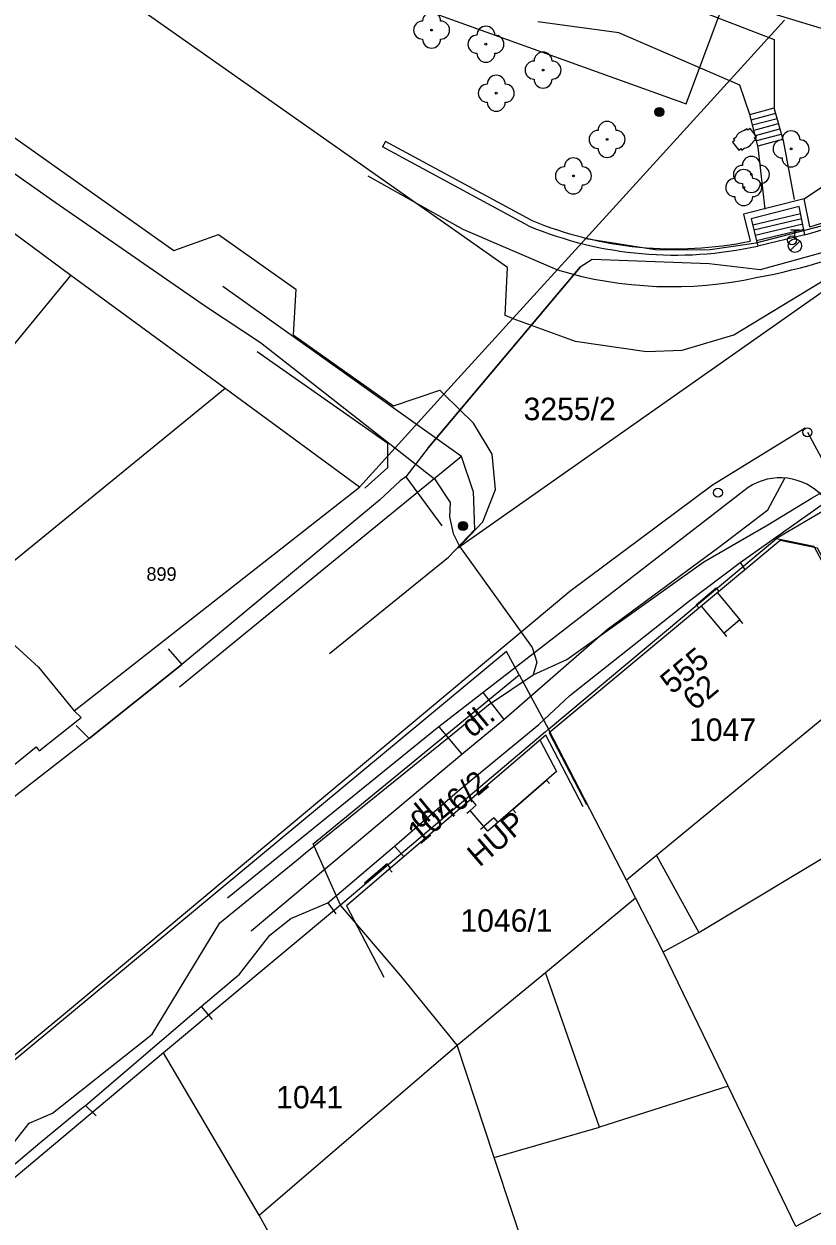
# Model space of a CAD drawing. Extents: x -601580 to 4, y -1204314 to 4.
# Drawn here: x -600094.3 to -600050.6, y -1203405.4 to -1203338.9 of the extents above; entities that cross this region are included whole.
import ezdxf

# ---------------------------------------------------------------- set-up
doc = ezdxf.new("R2010")
doc.units = 0
for name, color, linetype in [('00-KN-HRANICE PARCEL', 7, 'Continuous'), ('00-KN-PARC. CISLA', 7, 'Continuous'), ('00-KN-VNITRNI KRESBA', 7, 'Continuous'), ('00-POLOHOPIS', 7, 'Continuous'), ('00-SITE KOM. KABEL', 7, 'Continuous'), ('00-VAK-KANAL-POTRUBI', 7, 'Continuous'), ('00-VAK-VODA-RAD IGIS', 7, 'Continuous'), ('Vrstva 22', 7, 'Continuous'), ('Vrstva 25', 7, 'Continuous'), ('Vrstva 28', 7, 'Continuous'), ('Vrstva 6', 7, 'Continuous')]:
    doc.layers.add(name, color=color, linetype=linetype)

# ---------------------------------------------------------------- blocks, each defined once
blk = doc.blocks.new('6.01A_18')
at = {"layer": 'Vrstva 25'}
for radius in [0.25, 0.2, 0.15, 0.1, 0.05]:
    blk.add_circle((0, 0), radius, dxfattribs=at)
blk = doc.blocks.new('6.01A_1416')
at = {"layer": 'Vrstva 25'}
for radius in [0.25, 0.2, 0.15, 0.1, 0.05]:
    blk.add_circle((0, 0), radius, dxfattribs=at)
blk = doc.blocks.new('6.14A_536')
at = {"layer": 'Vrstva 28'}
blk.add_circle((0, 0), 0.25, dxfattribs=at)
blk = doc.blocks.new('6.14A_546')
at = {"layer": 'Vrstva 28'}
blk.add_circle((0, 0), 0.25, dxfattribs=at)
blk = doc.blocks.new('6.13_126')
at = {"layer": 'Vrstva 28'}
for p, q in [((-0.25, 0.875), (0.25, 0.875)), ((0, 0.375), (0, 0.875)), ((-0.258, -0.272), (0.272, 0.258))]:
    blk.add_line(p, q, dxfattribs=at)
blk.add_circle((0, 0), 0.375, dxfattribs=at)
blk = doc.blocks.new('6.14A_608')
at = {"layer": 'Vrstva 28'}
blk.add_circle((0, 0), 0.25, dxfattribs=at)
blk = doc.blocks.new('3.13_764')
at = {"layer": 'Vrstva 22'}
blk.add_circle((0, 0), 0.05, dxfattribs=at)
for centre, start, end in [((0, 0.5), 0, 180), ((-0.5, 0), 90, 270), ((0.5, 0), 270, 90), ((0, -0.5), 180, 0)]:
    blk.add_arc(centre, 0.5, start, end, dxfattribs=at)
blk = doc.blocks.new('3.13_766')
at = {"layer": 'Vrstva 22'}
blk.add_circle((0, 0), 0.05, dxfattribs=at)
for centre, start, end in [((0, 0.5), 0, 180), ((-0.5, 0), 90, 270), ((0.5, 0), 270, 90), ((0, -0.5), 180, 0)]:
    blk.add_arc(centre, 0.5, start, end, dxfattribs=at)
blk = doc.blocks.new('3.13_768')
at = {"layer": 'Vrstva 22'}
blk.add_circle((0, 0), 0.05, dxfattribs=at)
for centre, start, end in [((0, 0.5), 0, 180), ((-0.5, 0), 90, 270), ((0.5, 0), 270, 90), ((0, -0.5), 180, 0)]:
    blk.add_arc(centre, 0.5, start, end, dxfattribs=at)
blk = doc.blocks.new('3.13_770')
at = {"layer": 'Vrstva 22'}
blk.add_circle((0, 0), 0.05, dxfattribs=at)
for centre, start, end in [((0, 0.5), 0, 180), ((-0.5, 0), 90, 270), ((0.5, 0), 270, 90), ((0, -0.5), 180, 0)]:
    blk.add_arc(centre, 0.5, start, end, dxfattribs=at)
blk = doc.blocks.new('3.13_772')
at = {"layer": 'Vrstva 22'}
blk.add_circle((0, 0), 0.05, dxfattribs=at)
for centre, start, end in [((0, 0.5), 0, 180), ((-0.5, 0), 90, 270), ((0.5, 0), 270, 90), ((0, -0.5), 180, 0)]:
    blk.add_arc(centre, 0.5, start, end, dxfattribs=at)
blk = doc.blocks.new('3.13_774')
at = {"layer": 'Vrstva 22'}
blk.add_circle((0, 0), 0.05, dxfattribs=at)
for centre, start, end in [((0, 0.5), 0, 180), ((-0.5, 0), 90, 270), ((0.5, 0), 270, 90), ((0, -0.5), 180, 0)]:
    blk.add_arc(centre, 0.5, start, end, dxfattribs=at)
blk = doc.blocks.new('VCHOD_1184')
at = {"layer": 'Vrstva 6'}
blk.add_line((0, 0.25), (0, 0), dxfattribs=at)
blk = doc.blocks.new('VCHOD_1186')
at = {"layer": 'Vrstva 6'}
blk.add_line((0, 0.25), (0, 0), dxfattribs=at)
blk = doc.blocks.new('VCHOD_1190')
at = {"layer": 'Vrstva 6'}
blk.add_line((0, 0.25), (0, 0), dxfattribs=at)
blk = doc.blocks.new('VCHOD_1192')
at = {"layer": 'Vrstva 6'}
blk.add_line((0, 0.25), (0, 0), dxfattribs=at)
blk = doc.blocks.new('VCHOD_1194')
at = {"layer": 'Vrstva 6'}
blk.add_line((0, 0.25), (0, 0), dxfattribs=at)
blk = doc.blocks.new('VCHOD_1196')
at = {"layer": 'Vrstva 6'}
blk.add_line((0, 0.25), (0, 0), dxfattribs=at)
blk = doc.blocks.new('VCHOD_1198')
at = {"layer": 'Vrstva 6'}
blk.add_line((0, 0.25), (0, 0), dxfattribs=at)
blk = doc.blocks.new('3.13B')
at = {"layer": 'Vrstva 22'}
blk.add_circle((0, 0), 0.05, dxfattribs=at)
for centre, start, end in [((0, 0.5), 0, 180), ((-0.5, 0), 90, 270), ((0.5, 0), 270, 90), ((0, -0.5), 180, 0)]:
    blk.add_arc(centre, 0.5, start, end, dxfattribs=at)
blk = doc.blocks.new('3.13B_2')
at = {"layer": 'Vrstva 22'}
blk.add_circle((0, 0), 0.05, dxfattribs=at)
for centre, start, end in [((0, 0.5), 0, 180), ((-0.5, 0), 90, 270), ((0.5, 0), 270, 90), ((0, -0.5), 180, 0)]:
    blk.add_arc(centre, 0.5, start, end, dxfattribs=at)
blk = doc.blocks.new('3.13B_4')
at = {"layer": 'Vrstva 22'}
blk.add_circle((0, 0), 0.05, dxfattribs=at)
for centre, start, end in [((0, 0.5), 0, 180), ((-0.5, 0), 90, 270), ((0.5, 0), 270, 90), ((0, -0.5), 180, 0)]:
    blk.add_arc(centre, 0.5, start, end, dxfattribs=at)

msp = doc.modelspace()

# ---------------------------------------------------------------- linework, layer by layer
at = {"layer": '00-KN-HRANICE PARCEL'}
for p, q in [((-600052.12, -1203338.71), (-600063.14, -1203350.82)), ((-600063.14, -1203350.82), (-600067.18, -1203355.26)), ((-600071.01, -1203359.47), (-600067.18, -1203355.26)), ((-600071.01, -1203359.47), (-600075.7, -1203364.62)), ((-600042.39, -1203361.48), (-600052.56, -1203367.47)), ((-600091.52, -1203377.04), (-600075.7, -1203364.62)), ((-600065.2, -1203378.06), (-600052.56, -1203367.47)), ((-600066.83, -1203375.04), (-600065.2, -1203378.06)), ((-600076.74, -1203387.83), (-600086.56, -1203396.02)), ((-600086.56, -1203396.02), (-600096.33, -1203404.2))]:
    msp.add_line(p, q, dxfattribs=at)
for points in [[(-600140, -1203318.23), (-600138.91, -1203317.26), (-600137.57, -1203316.43), (-600136.11, -1203315.95), (-600133.54, -1203315.93), (-600130.69, -1203317.16), (-600130.97, -1203319.63), (-600120.34, -1203327.24), (-600117.91, -1203326.29), (-600112.74, -1203329.92), (-600113.21, -1203332.34), (-600107.76, -1203336.15), (-600105.34, -1203335.13), (-600101.46, -1203337.9), (-600101.76, -1203340.34), (-600086, -1203351.5), (-600083.51, -1203350.61), (-600079.22, -1203353.63), (-600079.38, -1203356.18), (-600073.8, -1203360.11), (-600071.24, -1203359.25), (-600071.01, -1203359.47)], [(-600063.14, -1203350.82), (-600059.16, -1203351.46), (-600056.24, -1203351.43), (-600053.69, -1203351.07), (-600049.98, -1203350.11), (-600046.24, -1203348.4), (-600042.49, -1203346.1), (-600032.5, -1203339.98), (-600017.63, -1203330.49)], [(-600090.39, -1203331.53), (-600057.56, -1203343.35), (-600055.67, -1203338.24)], [(-600067.18, -1203355.26), (-600067.61, -1203355.1), (-600067.48, -1203352.43), (-600093.01, -1203334.48)], [(-600075.7, -1203364.62), (-600083.15, -1203359.15), (-600091.71, -1203352.87), (-600096.44, -1203349.39)], [(-600067.18, -1203355.26), (-600063.72, -1203356.53), (-600059.77, -1203357.09), (-600057.79, -1203357.02), (-600054.93, -1203356.17), (-600043.68, -1203349.34), (-600070.24, -1203368.01), (-600068.85, -1203366.55), (-600068.15, -1203364.76), (-600068.34, -1203362.79), (-600069.37, -1203361.07), (-600071.01, -1203359.47)], [(-600052.56, -1203367.47), (-600050.49, -1203367.9), (-600046.79, -1203374.83), (-600043.37, -1203381.22)], [(-600096.93, -1203371.51), (-600093.51, -1203374.61), (-600091.52, -1203377.04)], [(-600066.83, -1203375.04), (-600067.53, -1203373.74), (-600144.54, -1203437.71), (-600187.44, -1203473.68)], [(-600076.74, -1203387.83), (-600078.27, -1203384.41), (-600066.83, -1203375.04)], [(-600103.09, -1203386.71), (-600100.16, -1203384.33), (-600093.64, -1203379.04), (-600093.46, -1203379.26), (-600091.14, -1203377.4), (-600091.52, -1203377.04)], [(-600065.2, -1203378.06), (-600065.38, -1203378.21), (-600076.74, -1203387.83)], [(-600058.84, -1203390.41), (-600060.38, -1203387.41), (-600060.88, -1203386.44), (-600065.2, -1203378.06)], [(-600058.84, -1203390.41), (-600056.86, -1203389.33), (-600043.37, -1203381.22)], [(-600070.27, -1203395.59), (-600073.39, -1203391.75), (-600076.74, -1203387.83)], [(-600051.49, -1203405.65), (-600055.24, -1203397.87), (-600058.84, -1203390.41)], [(-600074.85, -1203416.32), (-600078.71, -1203409.57), (-600079.76, -1203407.74), (-600081.26, -1203405.03), (-600086.56, -1203396.02)], [(-600065.17, -1203411.03), (-600068.22, -1203401.82), (-600070.27, -1203395.59)], [(-600034.9, -1203397.06), (-600045.17, -1203402.33), (-600051.49, -1203405.65)]]:
    msp.add_lwpolyline(points, dxfattribs=at)
at = {"layer": '00-KN-VNITRNI KRESBA'}
for p, q in [((-600100.78, -1203363.9), (-600091.71, -1203352.87)), ((-600083.15, -1203359.15), (-600097.32, -1203370.73)), ((-600046.79, -1203374.83), (-600059.21, -1203385.06)), ((-600059.21, -1203385.06), (-600060.88, -1203386.44)), ((-600059.21, -1203385.06), (-600056.86, -1203389.33)), ((-600065.38, -1203391.55), (-600060.38, -1203387.41)), ((-600070.27, -1203395.59), (-600065.38, -1203391.55)), ((-600062.38, -1203400.15), (-600065.38, -1203391.55)), ((-600081.26, -1203405.03), (-600070.27, -1203395.59)), ((-600055.24, -1203397.87), (-600062.38, -1203400.15)), ((-600068.22, -1203401.82), (-600062.38, -1203400.15))]:
    msp.add_line(p, q, dxfattribs=at)
at = {"layer": '00-POLOHOPIS'}
for p, q in [((-600062.868, -1203335.842), (-600052.683, -1203339.781)), ((-600061.31, -1203339.417), (-600065.806, -1203338.792)), ((-600054.599, -1203342.319), (-600061.31, -1203339.417)), ((-600052.683, -1203339.781), (-600052.681, -1203343.625)), ((-600054.036, -1203343.946), (-600054.599, -1203342.319)), ((-600054.036, -1203343.946), (-600052.681, -1203343.579)), ((-600052.681, -1203343.625), (-600052.187, -1203345.384)), ((-600053.571, -1203345.748), (-600054.036, -1203343.946)), ((-600053.957, -1203344.235), (-600052.602, -1203343.868)), ((-600053.879, -1203344.525), (-600052.524, -1203344.158)), ((-600053.8, -1203344.814), (-600052.445, -1203344.447)), ((-600053.722, -1203345.104), (-600052.367, -1203344.737)), ((-600074.242, -1203345.436), (-600074.409, -1203345.744)), ((-600066.159, -1203349.811), (-600074.242, -1203345.436)), ((-600053.643, -1203345.393), (-600052.288, -1203345.026)), ((-600053.565, -1203345.683), (-600052.21, -1203345.316)), ((-600052.187, -1203345.384), (-600051.571, -1203348.668)), ((-600051.03, -1203348.619), (-600045.758, -1203345.101)), ((-600066.31, -1203350.127), (-600074.409, -1203345.744)), ((-600053.184, -1203349.199), (-600053.571, -1203345.748)), ((-600075.222, -1203347.354), (-600069.956, -1203350.313)), ((-600051.219, -1203349.448), (-600053.878, -1203350.078)), ((-600051.159, -1203349.742), (-600053.807, -1203350.37)), ((-600051.099, -1203350.036), (-600053.736, -1203350.661)), ((-600069.956, -1203350.313), (-600064.711, -1203352.568)), ((-600051.039, -1203350.33), (-600053.664, -1203350.952)), ((-600050.979, -1203350.624), (-600053.593, -1203351.244)), ((-600070.033, -1203362.921), (-600083.284, -1203353.496)), ((-600070.033, -1203362.921), (-600085.676, -1203375.729)), ((-600069.393, -1203364.84), (-600070.033, -1203362.921)), ((-600053.032, -1203365.886), (-600052.085, -1203364.118)), ((-600054.135, -1203364.65), (-600071.294, -1203377.933)), ((-600069.393, -1203364.84), (-600069.319, -1203366.995)), ((-600055.757, -1203367.95), (-600053.032, -1203365.886)), ((-600069.319, -1203366.995), (-600070.763, -1203368.507)), ((-600061.952, -1203372.52), (-600055.757, -1203367.95)), ((-600077.356, -1203373.864), (-600070.763, -1203368.507)), ((-600057.004, -1203371.159), (-600055.91, -1203370.212)), ((-600055.742, -1203370.414), (-600055.91, -1203370.212)), ((-600056.854, -1203371.34), (-600057.004, -1203371.159)), ((-600054.589, -1203371.991), (-600055.467, -1203372.723)), ((-600067.685, -1203377.519), (-600061.952, -1203372.52)), ((-600068.837, -1203376.031), (-600067.685, -1203377.519)), ((-600071.294, -1203377.933), (-600083.01, -1203387.442)), ((-600071.294, -1203377.933), (-600070.02, -1203379.439)), ((-600070.02, -1203379.439), (-600067.685, -1203377.519)), ((-600081.699, -1203389.254), (-600070.02, -1203379.439)), ((-600067.188, -1203382.513), (-600065.311, -1203380.878)), ((-600068.795, -1203383.45), (-600069.555, -1203382.561)), ((-600068.243, -1203382.977), (-600068.795, -1203383.45)), ((-600068.243, -1203382.977), (-600068.017, -1203383.236)), ((-600074.166, -1203385.535), (-600075.408, -1203386.595)), ((-600074.04, -1203385.808), (-600075.158, -1203386.778)), ((-600073.967, -1203385.768), (-600074.166, -1203385.535))]:
    msp.add_line(p, q, dxfattribs=at)
for points in [[(-600053.856, -1203345.438), (-600053.73, -1203345.339), (-600053.79, -1203345.263), (-600053.658, -1203345.16), (-600054.01, -1203344.712), (-600054.14, -1203344.811), (-600054.198, -1203344.734), (-600054.325, -1203344.831)], [(-600054.818, -1203345.214), (-600054.946, -1203345.311), (-600054.885, -1203345.39), (-600055, -1203345.478), (-600054.648, -1203345.926), (-600054.538, -1203345.839), (-600054.476, -1203345.918), (-600054.35, -1203345.819)], [(-600050.712, -1203350.18), (-600051.03, -1203348.619), (-600054.385, -1203349.478), (-600054.019, -1203350.977)], [(-600050.979, -1203350.624), (-600051.3, -1203349.049), (-600053.963, -1203349.731), (-600053.593, -1203351.244)], [(-600075.389, -1203364.681), (-600074.116, -1203363.533), (-600074.113, -1203362.208), (-600081.374, -1203357.117)], [(-600048.946, -1203381.125), (-600044.51, -1203378.818), (-600046.574, -1203374.85), (-600050.29, -1203368.002), (-600052.345, -1203367.584), (-600065.165, -1203378.263), (-600063.101, -1203382.231)], [(-600055.837, -1203370.493), (-600054.589, -1203371.991), (-600055.467, -1203372.723), (-600056.715, -1203371.224)], [(-600063.285, -1203382.365), (-600065.349, -1203378.397), (-600076.411, -1203387.859), (-600074.347, -1203391.827)], [(-600065.676, -1203378.676), (-600064.761, -1203380.398), (-600068.567, -1203383.716), (-600069.555, -1203382.561), (-600069.213, -1203382.268), (-600069.474, -1203381.963)]]:
    msp.add_lwpolyline(points, dxfattribs=at)
for centre, radius, start, end in [((-600054.213, -1203345.485), 0.664, 99.77866, 155.87289), ((-600060.839, -1203316.797), 34.884, 286.87602, 306.72321), ((-600054.461, -1203345.164), 0.664, 279.58639, 335.68062), ((-600060.839, -1203316.797), 35.234, 286.25138, 306.72321), ((-600060.04, -1203318.739), 34.842, 280.51821, 306.87807), ((-600058.181, -1203330.525), 21.221, 247.4755, 282.48509), ((-600058.181, -1203330.525), 20.871, 247.52697, 281.50272), ((-600058.364, -1203331.35), 22.147, 253.34619, 282.20991), ((-600052.35, -1203367.314), 3.207, 41.95204, 123.83175)]:
    msp.add_arc(centre, radius, start, end, dxfattribs=at)
at = {"layer": '00-SITE KOM. KABEL'}
for points in [[(-600125.3, -1203327.75), (-600124.23, -1203327.51), (-600122.51, -1203328.65), (-600116.56, -1203332.81), (-600107.59, -1203339.13), (-600099.36, -1203344.04), (-600092.57, -1203348.81), (-600084.19, -1203354.62), (-600081.19, -1203356.59), (-600071.54, -1203364.17), (-600070.66, -1203365.48), (-600070.7, -1203366.27), (-600070.49, -1203367.19), (-600070.13, -1203367.93), (-600066.12, -1203373.53), (-600065.86, -1203374.34), (-600066.06, -1203375.04)], [(-600061.85, -1203334.84), (-600056.08, -1203337.01), (-600053.74, -1203338.05), (-600048.07, -1203339.77), (-600045.12, -1203338.86), (-600041.72, -1203341.8), (-600037.13, -1203342.83)], [(-600037.13, -1203342.83), (-600036.72, -1203343.88), (-600037.32, -1203344.98), (-600047.64, -1203350.96), (-600053.47, -1203352.57), (-600056.29, -1203352.23), (-600062.79, -1203351.99), (-600063.45, -1203352.41), (-600071.89, -1203362.45)], [(-600071.89, -1203362.45), (-600063.45, -1203352.41)], [(-600066.06, -1203375.04), (-600064.18, -1203374.18), (-600056.59, -1203368.77), (-600053.03, -1203366.72), (-600050.58, -1203365.21), (-600043.61, -1203361.27), (-600040.64, -1203359.61), (-600035.3, -1203356.56), (-600034.83, -1203356.8)], [(-600054.58, -1203368.81), (-600050.08, -1203365.62), (-600043.07, -1203361.02), (-600042.05, -1203360.13)], [(-600071.89, -1203362.45), (-600073.12, -1203364.06)], [(-600073.12, -1203364.06), (-600073.44, -1203364.28)], [(-600073.12, -1203364.06), (-600071.13, -1203366.78)], [(-600073.44, -1203364.28), (-600074.58, -1203365.35), (-600085.55, -1203374.47)], [(-600073.75, -1203384.55), (-600070.12, -1203381.41), (-600065.75, -1203377.79), (-600064.03, -1203376.18), (-600057.43, -1203370.97), (-600054.58, -1203368.81)], [(-600054.58, -1203368.81), (-600054.29, -1203369.24)], [(-600086.31, -1203373.59), (-600085.55, -1203374.47)], [(-600090.7, -1203378.58), (-600085.55, -1203374.47)], [(-600085.55, -1203374.47), (-600090.7, -1203378.58)], [(-600078.7, -1203384.94), (-600070.74, -1203378.5), (-600068.53, -1203376.7), (-600066.06, -1203375.04)], [(-600065.75, -1203377.79), (-600064.03, -1203376.18)], [(-600091.42, -1203377.85), (-600090.7, -1203378.58)], [(-600090.7, -1203378.58), (-600095.2, -1203382.08), (-600096.86, -1203383.48), (-600099.24, -1203385.52), (-600102.16, -1203389.69), (-600109.11, -1203394.47), (-600113.45, -1203397.68)], [(-600077.45, -1203387.69), (-600073.75, -1203384.55)], [(-600073.75, -1203384.55), (-600073.24, -1203385.13)], [(-600083.44, -1203388.81), (-600079.08, -1203385.26)], [(-600079.08, -1203385.26), (-600078.7, -1203384.94)], [(-600084.48, -1203393.44), (-600082.35, -1203391.65), (-600080.67, -1203389.48), (-600079.51, -1203388.56), (-600077.45, -1203387.69)], [(-600077.45, -1203387.69), (-600077, -1203388.31)], [(-600107.33, -1203411.85), (-600106.94, -1203411.55), (-600097.23, -1203403.13), (-600095.25, -1203401.47), (-600094.02, -1203399.92), (-600092.73, -1203399.36), (-600087.19, -1203394.98), (-600083.44, -1203388.81)], [(-600090.89, -1203398.94), (-600084.48, -1203393.44)], [(-600084.48, -1203393.44), (-600083.87, -1203394.16)], [(-600097.38, -1203404.34), (-600093.42, -1203401.02), (-600091.1, -1203399.09), (-600090.89, -1203398.94)], [(-600093.42, -1203401.02), (-600091.1, -1203399.09)], [(-600090.89, -1203398.94), (-600090.31, -1203399.51)]]:
    msp.add_lwpolyline(points, dxfattribs=at)
at = {"layer": '00-VAK-KANAL-POTRUBI'}
msp.add_lwpolyline([(-600050.972, -1203361.346), (-600056.105, -1203364.506), (-600064.02, -1203370.416), (-600092.111, -1203393.903), (-600104.009, -1203403.737), (-600108.975, -1203407.931), (-600128.264, -1203424.414), (-600153.386, -1203444.897), (-600177.667, -1203465.589), (-600188.287, -1203475.024), (-600202.096, -1203487.139), (-600222.466, -1203504.809), (-600241.526, -1203522.333), (-600258.815, -1203537.585), (-600279.708, -1203555.04), (-600298.296, -1203571.363), (-600318.679, -1203587.965), (-600335.723, -1203601.415), (-600365.844, -1203625.248), (-600367.698, -1203623.109), (-600372.217, -1203617.987)], dxfattribs=at)
at = {"layer": '00-VAK-VODA-RAD IGIS'}
for points in [[(-600050.972, -1203361.346), (-600056.105, -1203364.506), (-600064.02, -1203370.416), (-600092.111, -1203393.903), (-600104.009, -1203403.737), (-600108.975, -1203407.931), (-600128.264, -1203424.414), (-600153.386, -1203444.897), (-600177.667, -1203465.589), (-600188.287, -1203475.024), (-600202.096, -1203487.139), (-600222.466, -1203504.809), (-600241.526, -1203522.333), (-600258.815, -1203537.585), (-600279.708, -1203555.04), (-600298.296, -1203571.363), (-600318.679, -1203587.965), (-600335.723, -1203601.415), (-600365.844, -1203625.248), (-600367.698, -1203623.109), (-600372.217, -1203617.987)], [(-600050.837, -1203361.577), (-600045.812, -1203370.916), (-600028.761, -1203402.845), (-600021.577, -1203416.2), (-600013.12, -1203434.286)]]:
    msp.add_lwpolyline(points, dxfattribs=at)

# ---------------------------------------------------------------- block references
at = {"layer": '00-POLOHOPIS'}
for name, p in [('3.13B', (-600071.692, -1203339.258)), ('3.13B_2', (-600068.681, -1203340.044)), ('3.13_764', (-600065.505, -1203341.479)), ('3.13B_4', (-600068.103, -1203342.763)), ('3.13_766', (-600061.956, -1203345.325)), ('3.13_774', (-600051.747, -1203345.851)), ('3.13_772', (-600053.951, -1203347.269)), ('3.13_768', (-600063.824, -1203347.352)), ('3.13_770', (-600054.375, -1203348.001)), ('6.14A_608', (-600051.696, -1203350.92)), ('6.13_126', (-600051.535, -1203351.223)), ('6.14A_536', (-600050.837, -1203361.577)), ('6.14A_546', (-600055.809, -1203364.932))]:
    msp.add_blockref(name, p, dxfattribs=at)
at = {"layer": '00-POLOHOPIS', "rotation": -90.00000000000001}
msp.add_blockref('6.01A_18', (-600059.055, -1203343.801), dxfattribs=at)
at = {"layer": '00-POLOHOPIS'}
for name, p, xscale, yscale, rotation in [('6.01A_1416', (-600069.947, -1203366.78), 1.00000010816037, 1.00000010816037, 40.00021993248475), ('VCHOD_1184', (-600054.589, -1203371.991), 0.99999853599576, 0.9999985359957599, -140.18161857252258), ('VCHOD_1186', (-600055.467, -1203372.723), 0.99999853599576, 0.9999985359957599, -140.18161857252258), ('VCHOD_1192', (-600065.311, -1203380.878), 0.9999996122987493, 0.9999996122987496, -138.94175297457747), ('VCHOD_1198', (-600069.555, -1203382.561), 0.99999845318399, 0.9999984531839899, 130.52686331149), ('VCHOD_1194', (-600067.188, -1203382.513), 0.9999996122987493, 0.9999996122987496, -138.94175297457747), ('VCHOD_1196', (-600068.795, -1203383.45), 0.99999845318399, 0.9999984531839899, 130.52686331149), ('VCHOD_1190', (-600074.04, -1203385.808), 0.9999984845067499, 0.99999848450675, -139.05447294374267)]:
    msp.add_blockref(name, p, dxfattribs=dict(at, xscale=xscale, yscale=yscale, rotation=rotation))

# ---------------------------------------------------------------- texts
at = {"layer": '00-KN-PARC. CISLA'}
for s, height, p in [('3255/2', 1.25, (-600066.588, -1203360.91)), ('899', 0.75, (-600087.514, -1203369.82)), ('1047', 1.25, (-600057.407, -1203378.71)), ('1046/1', 1.25, (-600070.095, -1203389.3)), ('1041', 1.25, (-600080.314, -1203399.1))]:
    msp.add_text(s, height=height, dxfattribs=at).set_placement(p)
msp.add_text('1046/2', height=1.25, rotation=40, dxfattribs=at).set_placement((-600072.355, -1203384.502))
at = {"layer": '00-POLOHOPIS'}
for s, rotation, p in [('555', 39.79414, (-600058.345, -1203376.162)), ('62', 39.79414, (-600057.102, -1203377.078)), ('dl.', 39.42943, (-600069.43, -1203378.575)), ('dl.', 39.42943, (-600072.376, -1203383.635)), ('HUP', 40.59274, (-600069.037, -1203385.747))]:
    msp.add_text(s, height=1.25, rotation=rotation, dxfattribs=at).set_placement(p)

doc.saveas('drawing.dxf')
